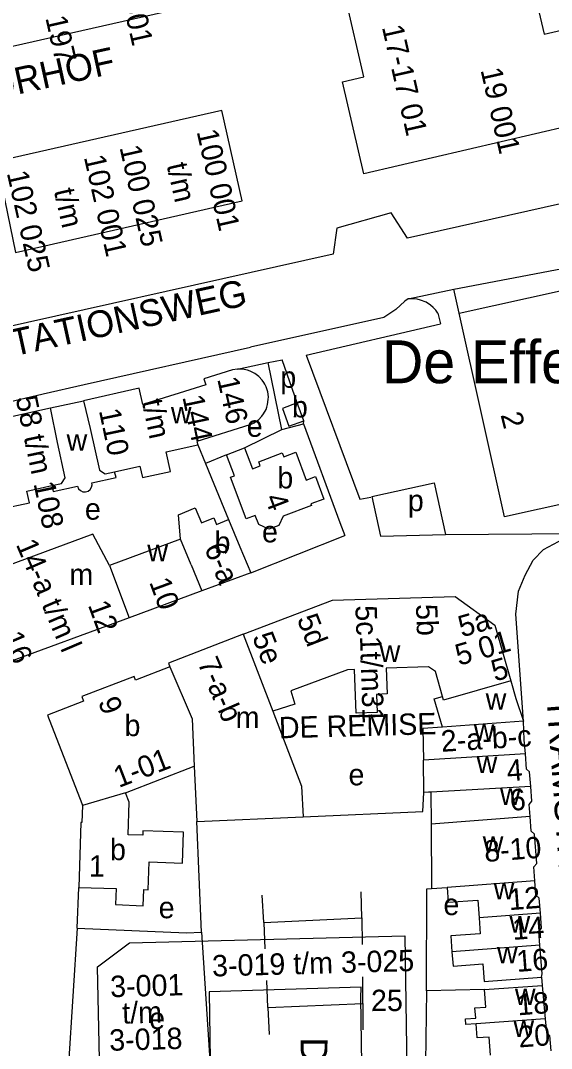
# Model space of a CAD drawing. Extents: x 160673 to 161924, y 382258 to 384145.
# Drawn here: x 161578.5 to 161677.7, y 383511.4 to 383703.4 of the extents above; entities that cross this region are included whole.
import ezdxf

# ---------------------------------------------------------------- set-up
doc = ezdxf.new("R2010")
doc.units = 0
for name, color, linetype in [('BLT_Basislijn', 7, 'Continuous'), ('BLT_Bebouwing', 7, 'Continuous'), ('BLT_Bebouwing_beschrifting', 7, 'Continuous'), ('BLT_Centroide', 7, 'Continuous'), ('BLT_Huisnummer', 7, 'Continuous'), ('BLT_Huisnummer_ tussenligend', 7, 'Continuous'), ('BLT_Huisnummer_reeks', 7, 'Continuous'), ('BLT_Huisnummer_zonder_bebouwing', 7, 'Continuous'), ('BLT_Onderdoorgang_en_onderverdeling', 7, 'Continuous'), ('BLT_Onderverdeling_panden', 7, 'Continuous'), ('BLT_Plantopo', 7, 'Continuous'), ('BLT_Straatnaam', 7, 'Continuous'), ('BLT_Straatnaam_verkleind', 7, 'Continuous')]:
    doc.layers.add(name, color=color, linetype=linetype)

msp = doc.modelspace()

# ---------------------------------------------------------------- linework, layer by layer
at = {"layer": 'BLT_Basislijn'}
for p, q in [((161650.93, 383651.44), (161659.47, 383653.24)), ((161660.46, 383648.78), (161659.47, 383653.24)), ((161656.48, 383648.78), (161656.96, 383646.77)), ((161590.41, 383635.47), (161621.48, 383642.41)), ((161630.2, 383632.01), (161627.4, 383640.07)), ((161582.76, 383633.73), (161590.41, 383635.47)), ((161631.34, 383628.08), (161631.43, 383628.66)), ((161611.6, 383624.17), (161613.03, 383620.69)), ((161616.96, 383622.33), (161613.03, 383620.69)), ((161613.03, 383620.69), (161614.62, 383616.86)), ((161614.62, 383616.86), (161617.37, 383610.23)), ((161657.88, 383607.4), (161684.77, 383607.61)), ((161612.28, 383533.15), (161611.41, 383553.78)), ((161589.07, 383533.87), (161589.42, 383541.48)), ((161623.93, 383534.92), (161623.67, 383540.04)), ((161642.26, 383535.83), (161642.16, 383540.67)), ((161623.93, 383534.92), (161642.26, 383535.83)), ((161642.26, 383535.83), (161642.32, 383530.85)), ((161623.93, 383534.92), (161624.16, 383530)), ((161624.72, 383519.05), (161624.51, 383524.09)), ((161642.47, 383519.83), (161642.47, 383524.79)), ((161665.2, 383522.39), (161654.31, 383522.14)), ((161624.72, 383519.05), (161642.47, 383519.83)), ((161624.72, 383519.05), (161624.94, 383514.01)), ((161642.47, 383519.83), (161642.47, 383514.86))]:
    msp.add_line(p, q, dxfattribs=at)
for points in [[(161748.83, 383689.69), (161749.31, 383684.86), (161650.8, 383662.81), (161647.76, 383667.52), (161637.6, 383664.67), (161636.93, 383659.78), (161564.43, 383643.62), (161563.17, 383648.74)], [(161659.47, 383653.24), (161688.55, 383658.79)], [(161650.93, 383651.44), (161650.29, 383651.04), (161648.61, 383649.47)], [(161654.26, 383650.83), (161653.24, 383651.21), (161652.57, 383651.37), (161651.88, 383651.46), (161651.19, 383651.46), (161650.93, 383651.44)], [(161656.48, 383648.78), (161656.07, 383649.33), (161655.6, 383649.84), (161655.07, 383650.28), (161654.26, 383650.83)], [(161648.61, 383649.47), (161646.38, 383647.99), (161621.48, 383642.41)], [(161631.89, 383640.94), (161656.96, 383646.77)], [(161631.89, 383640.94), (161641.9, 383614), (161643.94, 383614.41)], [(161619.05, 383638.33), (161624.75, 383639.55)], [(161624.75, 383639.55), (161627.4, 383640.07)], [(161627.33, 383627.04), (161624.75, 383639.55)], [(161522.03, 383622.11), (161525.56, 383620.28), (161582.76, 383633.73)], [(161627.33, 383627.04), (161631.34, 383628.08)], [(161631.34, 383628.08), (161638.18, 383609.67)], [(161620.34, 383623.61), (161627.33, 383627.04)], [(161644.12, 383614.49), (161655.75, 383617.06), (161657.88, 383607.4)], [(161644.12, 383614.49), (161645.76, 383607.14), (161657.88, 383607.4)], [(161638.18, 383609.67), (161639.08, 383607.25)], [(161621.51, 383600.25), (161639.08, 383607.25)], [(161672.44, 383572.56), (161671, 383592.52), (161671.52, 383596.81), (161672.76, 383599.82), (161674.29, 383602.6), (161676.22, 383604.62), (161679.9, 383606.62), (161684.77, 383607.61)], [(161631.27, 383554.67), (161653.65, 383555.68), (161653.83, 383559.25)], [(161654.31, 383522.14), (161654.37, 383541.24), (161655.3, 383541.28)], [(161589.07, 383533.87), (161587.46, 383508.5), (161587.28, 383501.59), (161587.16, 383498.2)], [(161589.07, 383533.87), (161609.48, 383533.02), (161612.28, 383533.15)], [(161612.28, 383533.15), (161614.63, 383497.72)], [(161654.31, 383522.14), (161654.16, 383508.71), (161654.24, 383501.51)]]:
    msp.add_lwpolyline(points, dxfattribs=at)
at = {"layer": 'BLT_Bebouwing'}
for p, q in [((161584.11, 383631.06), (161590.26, 383632.41)), ((161616.96, 383622.33), (161620.34, 383623.61)), ((161608.39, 383606.57), (161607.99, 383611.11)), ((161591.99, 383607.48), (161568.86, 383598.93)), ((161595.15, 383601.66), (161591.99, 383607.48)), ((161608.39, 383606.57), (161595.15, 383601.66)), ((161621.51, 383600.25), (161612.4, 383596.9)), ((161612.4, 383596.9), (161598.77, 383591.87)), ((161598.77, 383591.87), (161575.05, 383583.13)), ((161620.09, 383588.79), (161606.12, 383583.4)), ((161606.12, 383583.4), (161606.39, 383582.68)), ((161598.14, 383559.18), (161610.94, 383564.12)), ((161610.94, 383564.12), (161611.41, 383553.78)), ((161653.83, 383559.25), (161653.75, 383565.24)), ((161655.13, 383559.28), (161655.18, 383553.33)), ((161611.41, 383553.78), (161631.27, 383554.67)), ((161655.18, 383553.33), (161655.3, 383541.28)), ((161675.83, 383524.74), (161675.96, 383523.19)), ((161665.2, 383522.39), (161675.96, 383523.19))]:
    msp.add_line(p, q, dxfattribs=at)
for points in [[(161660.46, 383648.78), (161686.37, 383654.52), (161691.07, 383633.34)], [(161668.9, 383610.7), (161660.46, 383648.78)], [(161618.1, 383638.16), (161612.75, 383636.49), (161613.1, 383635.4), (161601.34, 383631.7), (161600.66, 383634.74), (161590.26, 383632.41)], [(161619.05, 383638.33), (161618.1, 383638.16)], [(161623.02, 383636.96), (161622.25, 383637.5), (161621.39, 383637.95), (161620.92, 383638.11), (161619.99, 383638.31), (161619.05, 383638.33)], [(161624.41, 383635), (161624.14, 383635.49), (161623.96, 383635.83), (161623.66, 383636.24), (161623.02, 383636.96)], [(161623.61, 383629.54), (161623.9, 383629.95), (161624.36, 383630.77), (161624.51, 383631.24), (161624.66, 383631.71), (161624.79, 383632.64), (161624.8, 383633.14), (161624.7, 383634.06), (161624.41, 383635)], [(161630.2, 383632.01), (161627.41, 383630.99), (161628.64, 383627.64), (161631.43, 383628.66)], [(161631.43, 383628.66), (161630.2, 383632.01)], [(161561, 383625.96), (161584.11, 383631.06)], [(161621.31, 383627.89), (161622.15, 383628.3), (161622.48, 383628.54), (161622.96, 383628.87), (161623.61, 383629.54)], [(161621.31, 383627.89), (161611.46, 383624.79), (161611.6, 383624.17)], [(161596.07, 383619.15), (161600.81, 383620.18), (161601.31, 383618.04), (161606.49, 383619.19), (161605.7, 383622.86), (161611.6, 383624.17)], [(161633.61, 383618.25), (161635.18, 383614.05), (161632.72, 383613.12), (161632.84, 383612.81), (161627.56, 383610.83), (161626.78, 383609.12), (161624.91, 383608.42), (161623.01, 383609.27), (161622.36, 383610.98), (161620.66, 383610.33), (161617.7, 383618.11), (161618.46, 383618.4), (161616.96, 383622.33)], [(161620.34, 383623.61), (161621.82, 383619.72), (161623.29, 383620.28), (161623.01, 383621), (161627.4, 383622.68), (161627.68, 383621.95), (161629.93, 383622.78), (161631.83, 383617.59), (161633.61, 383618.25)], [(161584.35, 383616.56), (161584.6, 383615.46), (161589.13, 383616.45), (161589.33, 383615.98), (161589.68, 383615.62), (161590.14, 383615.41), (161590.64, 383615.37), (161591.12, 383615.52), (161591.51, 383615.83), (161591.77, 383616.26), (161591.86, 383616.7), (161591.82, 383617.08), (161596.35, 383618.07), (161596.07, 383619.15)], [(161563.82, 383610.88), (161569.99, 383612.23), (161569.38, 383614.83), (161574.11, 383615.89), (161574.91, 383612.2), (161580.16, 383613.35), (161579.67, 383615.53), (161584.35, 383616.56)], [(161694.81, 383616.45), (161668.9, 383610.7)], [(161607.99, 383611.11), (161611.15, 383612.42), (161612.32, 383609.59), (161614.62, 383610.54), (161615.13, 383609.3), (161617.37, 383610.23)], [(161617.37, 383610.23), (161619.49, 383605.11), (161621.51, 383600.25)], [(161620.09, 383588.79), (161636.77, 383595.16), (161659.69, 383595.84), (161667.12, 383590.48), (161670.1, 383580.09)], [(161606.39, 383582.68), (161599.98, 383580.2), (161599.71, 383580.92), (161589.96, 383577.15), (161590.29, 383576.3), (161583.55, 383573.69), (161589.94, 383557.17), (161590.07, 383556.79)], [(161657.34, 383577.16), (161655.99, 383581.81), (161654.74, 383582.72), (161646.83, 383582.43), (161647, 383577.63), (161645.01, 383577.56), (161645.11, 383574.16), (161641.19, 383574.02), (161640.89, 383582.21), (161639.57, 383582.17), (161628.99, 383578.22), (161629.72, 383575.7), (161625.64, 383574.43)], [(161670.1, 383580.09), (161671.05, 383576.81), (161672.44, 383572.56)], [(161657.33, 383571.43), (161655.8, 383576.72), (161657.34, 383577.16)], [(161625.64, 383574.43), (161630.99, 383560.39), (161631.27, 383554.67)], [(161672.81, 383566.45), (161672.61, 383569.05), (161672.44, 383572.56)], [(161657.33, 383571.43), (161653.67, 383571.16), (161653.75, 383565.24)], [(161673.8, 383560.34), (161673.6, 383563.1), (161673.02, 383563.6), (161672.81, 383566.45)], [(161673.67, 383554.71), (161673.5, 383556.99), (161674.01, 383557.58), (161673.8, 383560.34)], [(161589.42, 383541.48), (161596.37, 383541.27), (161596.26, 383538.27), (161601.41, 383538.08), (161601.52, 383541.08), (161602.37, 383541.05), (161602.56, 383546.24), (161608.75, 383546.02), (161608.96, 383551.82), (161601.37, 383552.09), (161601.34, 383551.24), (161598.63, 383551.34), (161598.83, 383557.39), (161598.14, 383559.18)], [(161655.13, 383559.28), (161654.74, 383559.26), (161653.83, 383559.25)], [(161590.07, 383556.79), (161589.96, 383553.59), (161589.79, 383553.6), (161589.42, 383541.48)], [(161674.58, 383542.7), (161674.38, 383545.34), (161674.94, 383545.98), (161674.53, 383551.46), (161673.87, 383552.02), (161673.67, 383554.71)], [(161655.3, 383541.28), (161658.17, 383541.47)], [(161658.17, 383541.47), (161658.37, 383538.71), (161663.92, 383539.12), (161664.16, 383535.83)], [(161675.62, 383536.68), (161675.41, 383539.49), (161674.78, 383540.03), (161674.58, 383542.7)], [(161664.16, 383535.83), (161664.38, 383532.84), (161658.87, 383532.43), (161659.09, 383529.47)], [(161675.51, 383530.7), (161675.32, 383533.28), (161675.83, 383533.88), (161675.62, 383536.68)], [(161675.83, 383524.74), (161675.93, 383525.33), (161675.51, 383530.7)], [(161659.09, 383529.47), (161659.29, 383526.78), (161664.86, 383527.2), (161665.11, 383523.93), (161675.83, 383524.74)], [(161663.62, 383516.01), (161661.69, 383515.87), (161661.62, 383516.92), (161663.53, 383517.06), (161663.38, 383519), (161665.44, 383519.15), (161665.2, 383522.39)], [(161675.96, 383523.19), (161676.53, 383516.97)], [(161676.53, 383516.97), (161676.73, 383514.35), (161677.32, 383513.84), (161677.54, 383510.97)], [(161666.29, 383510.13), (161666.04, 383513.54), (161663.81, 383513.37), (161663.62, 383516.01)]]:
    msp.add_lwpolyline(points, dxfattribs=at)
at = {"layer": 'BLT_Onderdoorgang_en_onderverdeling'}
for points in [[(161590.26, 383632.41), (161591.49, 383627.2), (161593.23, 383619.41), (161594.3, 383618.77), (161596.07, 383619.15)], [(161584.35, 383616.56), (161586.18, 383616.96), (161586.82, 383617.99), (161585.44, 383624.58), (161584.11, 383631.06)], [(161670.1, 383580.09), (161657.54, 383576.45), (161657.34, 383577.16)]]:
    msp.add_lwpolyline(points, dxfattribs=at)
at = {"layer": 'BLT_Onderverdeling_panden'}
for p, q in [((161610.39, 383601.76), (161608.39, 383606.57)), ((161595.15, 383601.66), (161598.77, 383591.87)), ((161610.39, 383601.76), (161612.4, 383596.9)), ((161620.09, 383588.79), (161625.64, 383574.43)), ((161672.44, 383572.56), (161657.33, 383571.43)), ((161672.81, 383566.45), (161653.75, 383565.24)), ((161673.8, 383560.34), (161655.13, 383559.28)), ((161598.14, 383559.18), (161590.07, 383556.79)), ((161673.67, 383554.71), (161655.18, 383553.33)), ((161674.58, 383542.7), (161658.17, 383541.47)), ((161675.62, 383536.68), (161664.16, 383535.83)), ((161675.51, 383530.7), (161659.09, 383529.47)), ((161676.53, 383516.97), (161663.62, 383516.01))]:
    msp.add_line(p, q, dxfattribs=at)
msp.add_lwpolyline([(161606.39, 383582.68), (161610.57, 383573.01), (161610.94, 383564.12)], dxfattribs=at)
at = {"layer": 'BLT_Plantopo'}
for points in [[(161630.73, 383729.23), (161719.7, 383749.96), (161724.89, 383727.66), (161672.91, 383715.55), (161676.33, 383700.87), (161741.21, 383715.99), (161745.23, 383698.73), (161642.62, 383674.82), (161638.62, 383692), (161642.66, 383692.94), (161639.18, 383707.83), (161635.89, 383707.06)], [(161565.65, 383712.69), (161612.85, 383723.37), (161616.43, 383707.55), (161569.23, 383696.87)], [(161574.05, 383677.1), (161577.55, 383660.13), (161619.93, 383669.75), (161616.1, 383686.64)], [(161656.79, 383370.98), (161644.03, 383393.63), (161642.09, 383520.78), (161642.13, 383522.83), (161613.73, 383522.01), (161614.87, 383445.65), (161593.83, 383483.47), (161592.91, 383526.64), (161598.84, 383531.12), (161650.29, 383532.45), (161652.34, 383395.31), (161656.34, 383395.28)]]:
    msp.add_lwpolyline(points, close=True, dxfattribs=at)

# ---------------------------------------------------------------- texts
at = {"layer": 'BLT_Bebouwing_beschrifting'}
msp.add_text('De Effenaar', height=8, dxfattribs=at).set_placement((161646.02, 383635.68))
at = {"layer": 'BLT_Centroide'}
for s, p in [('p', (161627.03, 383634.82)), ('b', (161629.2, 383629.28)), ('w', (161606.59, 383628.19)), ('e', (161620.76, 383625.67)), ('w', (161587.11, 383623.07)), ('b', (161626.48, 383616.03)), ('p', (161650.85, 383611.78)), ('e', (161590.53, 383610.19)), ('e', (161623.61, 383605.95)), ('b', (161614.75, 383603.98)), ('w', (161602.19, 383602.42)), ('m', (161587.63, 383597.96)), ('w', (161645.58, 383583.62)), ('w', (161665.39, 383574.68)), ('b', (161597.93, 383569.75)), ('m', (161618.69, 383571.27)), ('w', (161663.16, 383568.91)), ('w', (161663.7, 383562.84)), ('e', (161639.77, 383560.56)), ('w', (161668.07, 383556.91)), ('b', (161595.22, 383546.58)), ('w', (161664.84, 383547.97)), ('w', (161666.88, 383539.25)), ('e', (161657.5, 383536.32)), ('e', (161604.31, 383535.73)), ('w', (161669.84, 383533.06)), ('w', (161667.51, 383527.31)), ('w', (161670.85, 383519.53)), ('e', (161602.54, 383515.03)), ('w', (161670.57, 383513.56))]:
    msp.add_text(s, height=4, dxfattribs=at).set_placement(p)
at = {"layer": 'BLT_Huisnummer'}
for s, rotation, p in [('2', 284.2355, (161668.14, 383629.8)), ('4', 290.8993, (161624.06, 383614.27)), ('10', 290.2959, (161602.5, 383598.54)), ('6', 4.2696, (161670.04, 383555.79)), ('1', 358.929, (161591.24, 383543.53)), ('14', 4.2663, (161670.5, 383531.67)), ('18', 4.263, (161671.43, 383517.58))]:
    msp.add_text(s, height=4, rotation=rotation, dxfattribs=at).set_placement(p)
at = {"layer": 'BLT_Huisnummer_ tussenligend'}
for s, rotation, p in [('4', 4.2751, (161669.45, 383561.3)), ('12', 4.2679, (161669.79, 383537.23)), ('16', 4.2663, (161671.25, 383525.69)), ('20', 4.263, (161671.63, 383511.58))]:
    msp.add_text(s, height=4, rotation=rotation, dxfattribs=at).set_placement(p)
at = {"layer": 'BLT_Huisnummer_reeks'}
for s, rotation, p in [('146', 282.6293, (161615.23, 383636.47)), ('58 t/m 108', 281.8294, (161577.57, 383632.95)), ('144', 281.8294, (161608.73, 383633.13)), (' t/m ', 281.8294, (161600.85, 383633.76)), ('110', 281.8294, (161593.14, 383630.58)), ('14-a t/m l', 293.1353, (161577.59, 383605.58)), ('6-a', 292.5674, (161612.77, 383604.93)), ('12', 290.2959, (161591.05, 383594.26)), ('5c', 272.0968, (161641.04, 383594.13)), ('5b', 272.0968, (161652.35, 383594.37)), ('5d', 291.1366, (161630.08, 383591.68)), ('5a', 16.2158, (161660.94, 383588.18)), ('16', 293.1353, (161574.93, 383588.35)), ('5e', 291.1366, (161621.73, 383588.3)), ('5 01', 16.2158, (161660.39, 383582.87)), ('1t/m31', 271.7608, (161641.91, 383588.41)), ('7-a-b', 293.3808, (161611.5, 383583.47)), ('5', 16.2158, (161667.11, 383579.92)), ('9', 291.1348, (161592.93, 383576.2)), ('2-a-b-c', 3.6269, (161657.14, 383566.81)), ('1-01', 21.1338, (161596.86, 383560.05)), ('8-10', 4.2679, (161665.25, 383546.24)), ('3-019 t/m 3-025', 1.5663, (161614.34, 383524.84)), ('3-001', 1.5663, (161595.3, 383520.97)), ('25', 0.2663, (161643.98, 383518.37)), ('t/m', 1.5663, (161597.55, 383516.03)), ('3-018', 1.5663, (161595.13, 383510.96))]:
    msp.add_text(s, height=4, rotation=rotation, dxfattribs=at).set_placement(p)
at = {"layer": 'BLT_Huisnummer_zonder_bebouwing'}
for s, p in [('101 001', (161595.17, 383717.32)), ('101 197', (161580.83, 383714.1)), ('17-17 01', (161645.99, 383702.22)), ('19 001', (161664.41, 383694.21)), ('100 001', (161611.38, 383682.71)), ('100 025', (161596.98, 383679.75)), ('102 001', (161590.32, 383677.93)), ('t/m', (161605.78, 383676.44)), ('102 025', (161575.92, 383674.98)), ('t/m', (161584.72, 383671.66))]:
    msp.add_text(s, height=4, rotation=282.7763, dxfattribs=at).set_placement(p)
at = {"layer": 'BLT_Straatnaam'}
for s, rotation, p in [('OUDE SPOORHOF', 12.3574, (161538.41, 383680.94)), ('STATIONSWEG', 12.3574, (161572.88, 383639.75)), ('TRAMSTRAAT', 274.1772, (161676.75, 383576.84)), ('DE BOSLOOP', 269.769, (161630.85, 383513.47))]:
    msp.add_text(s, height=5, rotation=rotation, dxfattribs=at).set_placement(p)
at = {"layer": 'BLT_Straatnaam_verkleind'}
msp.add_text('DE REMISE', height=4, rotation=1.548, dxfattribs=at).set_placement((161626.82, 383569.33))

doc.saveas('drawing.dxf')
